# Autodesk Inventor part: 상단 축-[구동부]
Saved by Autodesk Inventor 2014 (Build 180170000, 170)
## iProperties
Created: 2025-02
Part Number: 상단 축-[구동부]
Material: 강철, 탄소
Document SubType Name: Modeling
Designer: dg
Density: 7.87 g/cm^3
Appearance: 반연마
Mass: 53.8715 g
Surface Area: 29.9366 cm^2
Volume: 6.84518 cm^3
Author: jhkim
Creation Date: 2025-01-06
Sending System: Autodesk Inventor 2025
Preprocessor: ST-DEVELOPER v20
Author: dg
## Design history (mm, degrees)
node "상단 축1"
node "솔리드1"
node "기준1"
